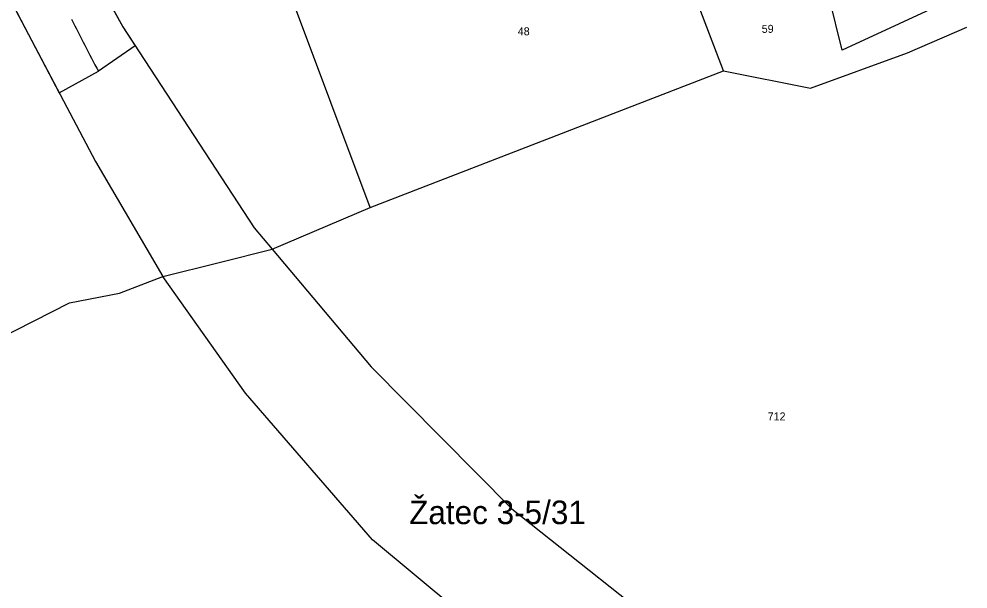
# Model space of a CAD drawing. Extents: x -812394 to -807601, y -1013097 to -1009266.
# Drawn here: x -809827.1 to -809625.5, y -1011167.6 to -1011046.5 of the extents above; entities that cross this region are included whole.
import ezdxf

# ---------------------------------------------------------------- set-up
doc = ezdxf.new("R2010")
doc.units = 0
for name, color, linetype in [('KLADY_ZMVM', 7, 'Continuous'), ('KN_HRANICE', 7, 'Continuous'), ('KN_PARCELY', 7, 'Continuous'), ('obvod_stavby', 7, 'Continuous'), ('SO02 - Železniční svršek', 7, 'Continuous')]:
    doc.layers.add(name, color=color, linetype=linetype)

msp = doc.modelspace()

# ---------------------------------------------------------------- linework, layer by layer
at = {"layer": 'KN_HRANICE'}
for p, q in [((-809817.83, -1011024.91), (-809805.06, -1011048.21)), ((-809836.26, -1011028.53), (-809810.89, -1011076.81)), ((-809652.22, -1011053.19), (-809658.63, -1011027.44)), ((-809752.49, -1011086.54), (-809770.25, -1011039.27)), ((-809677.42, -1011057.54), (-809684.4, -1011039.22)), ((-809625.71, -1011040.87), (-809652.22, -1011053.19)), ((-809805.06, -1011048.21), (-809777.13, -1011090.84)), ((-809638.37, -1011053.74), (-809625.71, -1011048.27)), ((-809658.97, -1011061.19), (-809638.37, -1011053.74)), ((-809752.49, -1011086.54), (-809677.42, -1011057.54)), ((-809677.42, -1011057.54), (-809658.97, -1011061.19)), ((-809810.89, -1011076.81), (-809796.54, -1011101.19)), ((-809773.31, -1011095.41), (-809752.49, -1011086.54)), ((-809777.13, -1011090.84), (-809773.31, -1011095.41)), ((-809784.6, -1011098.22), (-809773.31, -1011095.41)), ((-809796.54, -1011101.19), (-809784.6, -1011098.22)), ((-809779.01, -1011125.97), (-809796.54, -1011101.19)), ((-809751.99, -1011157.11), (-809779.01, -1011125.97)), ((-809719.22, -1011184.3), (-809751.99, -1011157.11))]:
    msp.add_line(p, q, dxfattribs=at)
for points in [[(-809773.31, -1011095.41), (-809752.3, -1011120.38), (-809722.41, -1011150.52), (-809685.06, -1011180.11), (-809638.61, -1011207.44), (-809624.45, -1011211.08)], [(-809925.02, -1011131.63), (-809914.36, -1011132.31), (-809886.15, -1011132.43), (-809869.35, -1011129.81), (-809831.58, -1011114.54), (-809816.37, -1011106.77), (-809805.79, -1011104.77), (-809796.54, -1011101.19)]]:
    msp.add_lwpolyline(points, dxfattribs=at)
at = {"layer": 'obvod_stavby'}
for points in [[(-809819.54, -1010907.65), (-809819.54, -1010907.65), (-809817.34, -1010954.54), (-809819.55, -1010971.16), (-809814.76, -1010988.43), (-809814.4, -1010991.28), (-809823.56, -1010994.65), (-809817.83, -1011024.91), (-809805.06, -1011048.21), (-809802.44, -1011052.2)], [(-809865.72, -1010986.44), (-809864.77, -1010992.44), (-809859.52, -1010995.97), (-809854.51, -1011000.24), (-809850.32, -1011003.33), (-809836.26, -1011028.53), (-809823.58, -1011052.67), (-809818.58, -1011062.18)], [(-809802.44, -1011052.2), (-809810.25, -1011057.62)], [(-809818.58, -1011062.18), (-809810.21, -1011057.6)]]:
    msp.add_lwpolyline(points, dxfattribs=at)
at = {"layer": 'SO02 - Železniční svršek'}
msp.add_arc((-809483.92, -1010882.18), 370.5, 206.3405, 208.2649, dxfattribs=at)

# ---------------------------------------------------------------- texts
at = {"layer": 'KLADY_ZMVM'}
msp.add_text('Žatec 3-5/31', height=5, dxfattribs=at).set_placement((-809744.22, -1011153.78))
at = {"layer": 'KN_PARCELY'}
for s, p in [('48', (-809721.15, -1011050)), ('59', (-809669.32, -1011049.48)), ('712', (-809668.06, -1011131.76))]:
    msp.add_text(s, height=1.7, dxfattribs=at).set_placement(p)

doc.saveas('drawing.dxf')
